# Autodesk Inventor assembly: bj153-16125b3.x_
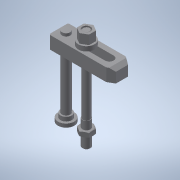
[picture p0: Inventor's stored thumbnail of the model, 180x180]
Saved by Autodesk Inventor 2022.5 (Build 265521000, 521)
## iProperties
Part Number: bj153-16125b3.x_
Material: 一般
Document SubType Name: Assembly
Designer: ImaoCorp
Sending System: SOLIDWORKS 2017-2017317
MC: AMD64
MC_MODEL: Intel64 Family 6 Model 60 Stepping 3, GenuineIntel
OS: Windows_NT
FRU: Parasolid Version 29.0, build 201,  4-17-2017
FORMAT: text
GUISE: transmit
KEY: bj153-16125b3
FILE: bj153-16125b3.x_t
DATE: Fri Mar 15 10:23:05 2019
Author: ImaoCorp
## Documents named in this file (6)
- X:\14_SW2022-Inv2022\00_全2023-1023新製品(TCC)まで\b\bj153-16125b3\BJ153-16125B3.iam
- X:\14_SW2022-Inv2022\00_全2023-1023新製品(TCC)まで\b\bj153-16125b3\bj153-16125b3_01.ipt
- X:\14_SW2022-Inv2022\00_全2023-1023新製品(TCC)まで\b\bj153-16125b3\bj153-16125b3_02.ipt
- X:\14_SW2022-Inv2022\00_全2023-1023新製品(TCC)まで\b\bj153-16125b3\bj153-16125b3_03.ipt
- X:\14_SW2022-Inv2022\00_全2023-1023新製品(TCC)まで\b\bj153-16125b3\bj153-16125b3_04.ipt
- X:\14_SW2022-Inv2022\00_全2023-1023新製品(TCC)まで\b\bj153-16125b3\bj153-16125b3_05.ipt
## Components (5 placed, 5 different names)
1. bj153-16125b3_01
2. bj153-16125b3_02
3. bj153-16125b3_03
4. bj153-16125b3_04
5. bj153-16125b3_05
